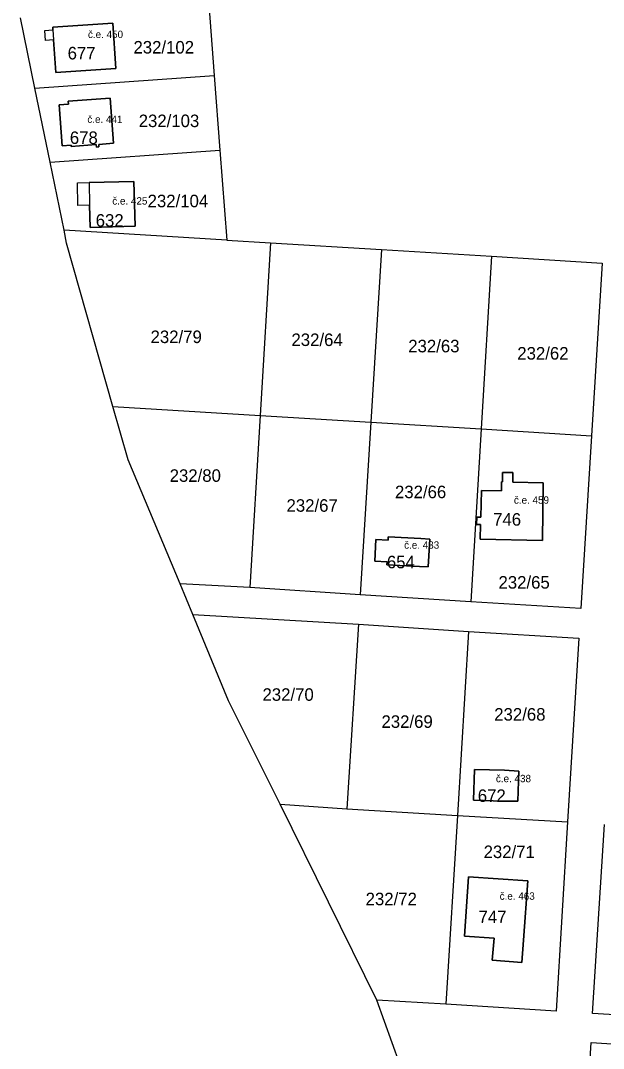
# Model space of a CAD drawing. Extents: x -887272 to -877616, y -1026687 to -1019819.
# Drawn here: x -882001.6 to -881922.6, y -1023755.1 to -1023615.5 of the extents above; entities that cross this region are included whole.
import ezdxf

# ---------------------------------------------------------------- set-up
doc = ezdxf.new("R2010")
doc.units = 0
for name, color, linetype in [('Definiční body', 7, 'Continuous'), ('Hranice parcel', 7, 'Continuous'), ('Parcelní čísla', 7, 'Continuous'), ('Polygon budovy', 7, 'Continuous'), ('Vnitřní kresba', 7, 'Continuous')]:
    doc.layers.add(name, color=color, linetype=linetype)

msp = doc.modelspace()

# ---------------------------------------------------------------- linework, layer by layer
at = {"layer": 'Hranice parcel'}
for p, q in [((-881976.12, -1023613.34), (-881975.38, -1023622.97)), ((-881999.69, -1023624.69), (-882001.64, -1023615.16)), ((-881999.69, -1023624.69), (-881975.38, -1023622.97)), ((-881975.38, -1023622.97), (-881974.6, -1023633.13)), ((-881997.63, -1023634.76), (-881999.69, -1023624.69)), ((-881997.63, -1023634.76), (-881974.6, -1023633.13)), ((-881974.6, -1023633.13), (-881973.66, -1023645.33)), ((-881995.74, -1023643.96), (-881997.63, -1023634.76)), ((-881973.66, -1023645.33), (-881995.74, -1023643.96)), ((-881973.66, -1023645.33), (-881967.74, -1023645.7)), ((-881967.74, -1023645.7), (-881969.15, -1023669.15)), ((-881967.74, -1023645.7), (-881952.7, -1023646.62)), ((-881952.7, -1023646.62), (-881954.14, -1023670.06)), ((-881952.7, -1023646.62), (-881937.78, -1023647.52)), ((-881937.78, -1023647.52), (-881939.18, -1023670.97)), ((-881989.11, -1023667.93), (-881969.15, -1023669.15)), ((-881969.15, -1023669.15), (-881970.55, -1023692.51)), ((-881969.15, -1023669.15), (-881954.14, -1023670.06)), ((-881954.14, -1023670.06), (-881955.58, -1023693.49)), ((-881954.14, -1023670.06), (-881939.18, -1023670.97)), ((-881939.18, -1023670.97), (-881940.59, -1023694.43)), ((-881939.18, -1023670.97), (-881924.21, -1023671.89)), ((-881970.55, -1023692.51), (-881980.01, -1023691.98)), ((-881978.29, -1023696.16), (-881980.01, -1023691.98)), ((-881955.58, -1023693.49), (-881970.55, -1023692.51)), ((-881940.59, -1023694.43), (-881955.58, -1023693.49)), ((-881978.29, -1023696.16), (-881955.81, -1023697.47)), ((-881955.81, -1023697.47), (-881957.38, -1023722.54)), ((-881955.81, -1023697.47), (-881940.88, -1023698.48)), ((-881940.88, -1023698.48), (-881942.4, -1023723.43)), ((-881953.3, -1023748.53), (-881966.43, -1023721.93)), ((-881966.43, -1023721.93), (-881957.38, -1023722.54)), ((-881957.38, -1023722.54), (-881942.4, -1023723.43)), ((-881942.4, -1023723.43), (-881943.98, -1023749.08)), ((-881942.4, -1023723.43), (-881927.45, -1023724.33)), ((-881943.98, -1023749.08), (-881953.3, -1023748.53))]:
    msp.add_line(p, q, dxfattribs=at)
for points in [[(-881997.26, -1023616.79), (-881997.28, -1023616.44), (-881989.15, -1023615.89), (-881988.74, -1023622.03), (-881996.87, -1023622.57), (-881997.17, -1023618.13), (-881998.27, -1023618.21), (-881998.36, -1023616.86), (-881997.26, -1023616.79)], [(-881995.19, -1023626.47), (-881989.49, -1023626.05), (-881989.05, -1023632.19), (-881991.04, -1023632.34), (-881991.01, -1023632.69), (-881991.36, -1023632.71), (-881991.38, -1023632.36), (-881994.77, -1023632.61), (-881994.78, -1023632.43), (-881995.99, -1023632.52), (-881996.4, -1023626.95), (-881995.16, -1023626.87), (-881995.19, -1023626.47)], [(-881992.27, -1023640.59), (-881993.86, -1023640.63), (-881993.94, -1023637.57), (-881992.34, -1023637.53), (-881986.28, -1023637.37), (-881986.12, -1023643.44), (-881992.19, -1023643.6), (-881992.27, -1023640.59)], [(-881989.11, -1023667.93), (-881995.4, -1023645.73), (-881995.74, -1023643.96)], [(-881937.78, -1023647.52), (-881922.75, -1023648.47), (-881924.21, -1023671.89)], [(-881980.01, -1023691.98), (-881987.07, -1023675.17), (-881989.11, -1023667.93)], [(-881924.21, -1023671.89), (-881925.66, -1023695.35), (-881940.59, -1023694.43)], [(-881939.24, -1023683.95), (-881939.79, -1023683.94), (-881939.77, -1023682.94), (-881939.22, -1023682.95), (-881939.14, -1023679.32), (-881936.43, -1023679.37), (-881936.4, -1023678.17), (-881936.28, -1023678.17), (-881936.26, -1023676.89), (-881934.86, -1023676.9), (-881934.88, -1023678.2), (-881930.78, -1023678.28), (-881930.87, -1023686.11), (-881939.29, -1023685.93), (-881939.24, -1023683.95)], [(-881951.79, -1023686.06), (-881951.77, -1023685.63), (-881947.36, -1023685.86), (-881946.14, -1023685.93), (-881946.34, -1023689.71), (-881947.54, -1023689.65), (-881951.97, -1023689.42), (-881951.94, -1023688.99), (-881953.61, -1023688.9), (-881953.46, -1023685.97), (-881951.79, -1023686.06)], [(-881966.43, -1023721.93), (-881973.45, -1023707.87), (-881978.29, -1023696.16)], [(-881940.88, -1023698.48), (-881925.91, -1023699.39), (-881927.45, -1023724.33)], [(-881936.17, -1023721.5), (-881940.21, -1023721.38), (-881940.08, -1023717.19), (-881936.02, -1023717.3), (-881934.08, -1023717.43), (-881934.2, -1023721.52), (-881936.17, -1023721.5)], [(-881927.45, -1023724.33), (-881929.02, -1023750.02), (-881943.98, -1023749.08)], [(-881909.11, -1023751.24), (-881924.05, -1023750.31), (-881922.43, -1023724.66)], [(-881933.43, -1023740.38), (-881933.65, -1023743.41), (-881937.69, -1023743.11), (-881937.41, -1023740.1), (-881941.43, -1023739.83), (-881940.88, -1023731.79), (-881932.84, -1023732.34), (-881933.43, -1023740.38)], [(-881934.53, -1023818.08), (-881937.73, -1023791.96), (-881953.3, -1023748.53)], [(-881925.8, -1023779.26), (-881924.27, -1023754.29), (-881909.32, -1023755.23)]]:
    msp.add_lwpolyline(points, dxfattribs=at)
at = {"layer": 'Polygon budovy'}
for points in [[(-881996.87, -1023622.57), (-881988.74, -1023622.03), (-881989.15, -1023615.89), (-881997.28, -1023616.44), (-881997.26, -1023616.79), (-881997.17, -1023618.13)], [(-881991.38, -1023632.36), (-881991.36, -1023632.71), (-881991.01, -1023632.69), (-881991.04, -1023632.34), (-881989.05, -1023632.19), (-881989.49, -1023626.05), (-881995.19, -1023626.47), (-881995.16, -1023626.87), (-881996.4, -1023626.95), (-881995.99, -1023632.52), (-881994.78, -1023632.43), (-881994.77, -1023632.61)], [(-881992.19, -1023643.6), (-881986.12, -1023643.44), (-881986.28, -1023637.37), (-881992.34, -1023637.53), (-881992.27, -1023640.59)], [(-881936.43, -1023679.37), (-881939.14, -1023679.32), (-881939.22, -1023682.95), (-881939.77, -1023682.94), (-881939.79, -1023683.94), (-881939.24, -1023683.95), (-881939.29, -1023685.93), (-881930.87, -1023686.11), (-881930.78, -1023678.28), (-881934.88, -1023678.2), (-881934.86, -1023676.9), (-881936.26, -1023676.89), (-881936.28, -1023678.17), (-881936.4, -1023678.17)], [(-881951.77, -1023685.63), (-881951.79, -1023686.06), (-881953.46, -1023685.97), (-881953.61, -1023688.9), (-881951.94, -1023688.99), (-881951.97, -1023689.42), (-881947.54, -1023689.65), (-881946.34, -1023689.71), (-881946.14, -1023685.93), (-881947.36, -1023685.86)], [(-881940.08, -1023717.19), (-881940.21, -1023721.38), (-881936.17, -1023721.5), (-881934.2, -1023721.52), (-881934.08, -1023717.43), (-881936.02, -1023717.3)], [(-881941.43, -1023739.83), (-881937.41, -1023740.1), (-881937.69, -1023743.11), (-881933.65, -1023743.41), (-881933.43, -1023740.38), (-881932.84, -1023732.34), (-881940.88, -1023731.79)]]:
    msp.add_lwpolyline(points, close=True, dxfattribs=at)
at = {"layer": 'Vnitřní kresba'}
for p, q in [((-881997.26, -1023616.79), (-881997.17, -1023618.13)), ((-881992.34, -1023637.53), (-881992.27, -1023640.59))]:
    msp.add_line(p, q, dxfattribs=at)

# ---------------------------------------------------------------- texts
at = {"layer": 'Definiční body'}
for s, p in [('č.e. 450', (-881992.5, -1023617.9)), ('č.e. 441', (-881992.58, -1023629.43)), ('č.e. 425', (-881989.2, -1023640.51)), ('č.e. 459', (-881934.73, -1023681.12)), ('č.e. 433', (-881949.62, -1023687.23)), ('č.e. 438', (-881937.17, -1023718.93)), ('č.e. 463', (-881936.66, -1023734.89))]:
    msp.add_text(s, height=1, dxfattribs=at).set_placement(p)
at = {"layer": 'Parcelní čísla'}
for s, p in [('232/102', (-881986.33, -1023620)), ('677', (-881995.26, -1023620.8)), ('232/103', (-881985.62, -1023629.99)), ('678', (-881994.96, -1023632.28)), ('232/104', (-881984.41, -1023640.87)), ('632', (-881991.45, -1023643.51)), ('232/79', (-881984.01, -1023659.31)), ('232/64', (-881964.9, -1023659.71)), ('232/63', (-881949.06, -1023660.57)), ('232/62', (-881934.27, -1023661.55)), ('232/80', (-881981.42, -1023678.15)), ('232/66', (-881950.86, -1023680.37)), ('232/67', (-881965.57, -1023682.21)), ('746', (-881937.55, -1023684.1)), ('654', (-881951.96, -1023689.89)), ('232/65', (-881936.82, -1023692.65)), ('232/70', (-881968.83, -1023707.88)), ('232/68', (-881937.4, -1023710.57)), ('232/69', (-881952.69, -1023711.55)), ('672', (-881939.63, -1023721.61)), ('232/71', (-881938.84, -1023729.23)), ('232/72', (-881954.84, -1023735.63)), ('747', (-881939.52, -1023738.05))]:
    msp.add_text(s, height=1.7, dxfattribs=at).set_placement(p)

doc.saveas('drawing.dxf')
